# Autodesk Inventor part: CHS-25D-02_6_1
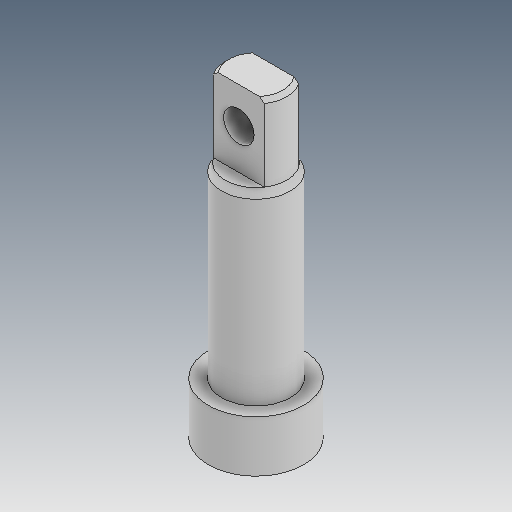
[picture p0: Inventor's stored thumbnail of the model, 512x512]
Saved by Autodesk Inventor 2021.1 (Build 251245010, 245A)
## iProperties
Created: 2019-05
Part Number: CHS-25D-02_6_1
Material: Ogólny
Document SubType Name: Modeling
Designer: user
Density: 1 g/cm^3
Appearance: Domyślna
Author: user
Revision Number: ÈÎºÎ
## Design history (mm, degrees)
feature "ÊäÈë1"
feature "ÊäÈë2"
node "Bryła1"
node "Bryła2"
